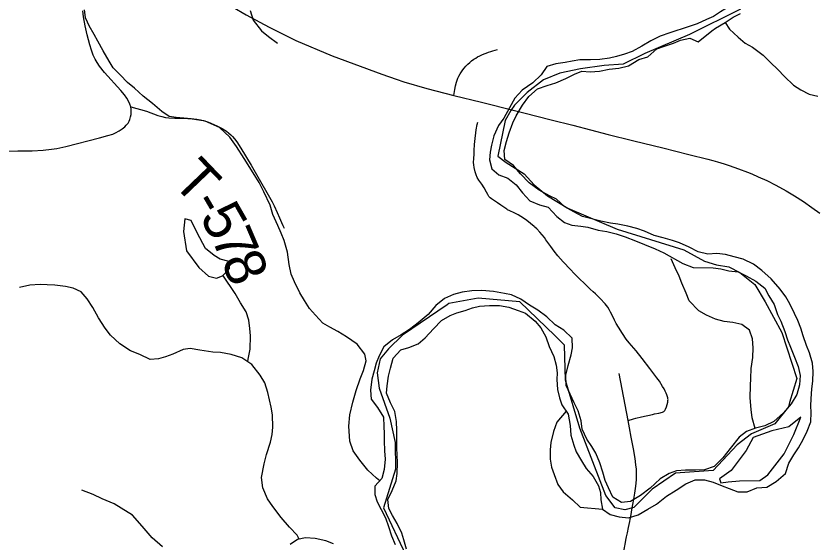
# Model space of a CAD drawing. Extents: x 1451455 to 1749751, y 218250 to 574981.
# Drawn here: x 1559745 to 1565644, y 318123 to 322002 of the extents above; entities that cross this region are included whole.
import ezdxf

# ---------------------------------------------------------------- set-up
doc = ezdxf.new("R2010")
doc.units = 0
for name, color, linetype in [('GM_X_County_Road', 7, 'Continuous'), ('GM_X_Major_River', 7, 'Continuous'), ('GM_X_Minor_Lake', 7, 'Continuous'), ('GM_X_Minor_River', 7, 'Continuous'), ('GM_X_State_Route', 7, 'Continuous'), ('GM_X_Township', 7, 'Continuous'), ('GM_X_Township_Road', 7, 'Continuous'), ('GM_X_Township_Road_Text', 7, 'Continuous'), ('GM_X_Township_ROW', 7, 'Continuous')]:
    doc.layers.add(name, color=color, linetype=linetype)

msp = doc.modelspace()

# ---------------------------------------------------------------- linework, layer by layer
at = {"layer": 'GM_X_County_Road'}
for points in [[(1560589.2, 321333.9), (1560583.5, 321352.9), (1560573.9, 321374.5), (1560560.8, 321397.8), (1560543.4, 321422.1), (1560517.9, 321452.6), (1560396.1, 321585.5), (1560360, 321631.9), (1560341.9, 321658.7), (1560327.5, 321684), (1560314.1, 321713.5), (1560300.5, 321750.1), (1560288, 321790.6), (1560269.7, 321863.6), (1560254.6, 321930.7), (1560242.7, 321994.9), (1560237.4, 322040.2)], [(1559488.5, 321004.8), (1559757.4, 321008.3), (1559862.6, 321010.4), (1559944.6, 321015), (1560007.2, 321022.2), (1560046, 321027.7), (1560110.4, 321041.4), (1560358.5, 321104), (1560422, 321121.4), (1560456.7, 321132.6), (1560478.1, 321141.7), (1560504.6, 321155.8), (1560527, 321170.4), (1560545.3, 321185.3), (1560557.1, 321197.3), (1560569.7, 321213.2), (1560577.8, 321228), (1560583.1, 321240.5), (1560588.7, 321259.9), (1560591.7, 321276.6), (1560593.2, 321296.7), (1560591.9, 321316.5), (1560589.2, 321333.9)]]:
    msp.add_lwpolyline(points, dxfattribs=at)
at = {"layer": 'GM_X_Major_River'}
for points in [[(1564997.1, 322072.7), (1564934.2, 322031.8), (1564881.6, 321998.7), (1564831.1, 321975.5), (1564760.5, 321944.8), (1564696, 321921.9), (1564559.6, 321877.9)], [(1564869.4, 321893.8), (1564896, 321912.3), (1564966.9, 321955.1), (1565027.6, 321994), (1565080.2, 322021.1)], [(1564559.6, 321877.9), (1564489.4, 321852.9), (1564421.1, 321819.9), (1564354.6, 321780.9), (1564282.2, 321741.9), (1564226, 321720.8), (1564167.8, 321703.6), (1564115.8, 321692.4), (1564045.8, 321681.5), (1563975.9, 321678.5), (1563898.1, 321679.7), (1563840, 321670.6), (1563790, 321659.3), (1563720, 321650.4), (1563653.8, 321631.4), (1563613, 321567.9), (1563550.2, 321510.8), (1563471.6, 321456), (1563418.8, 321396.7), (1563379.8, 321325.2), (1563338.7, 321249.8), (1563298, 321196.3), (1563264.9, 321120.7), (1563245.9, 321051), (1563237.1, 320999), (1563232.3, 320943), (1563249.2, 320876.7), (1563300.4, 320831.9), (1563365.9, 320808.8), (1563429.1, 320759.8), (1563474, 320699.1), (1563529, 320640.2), (1563600.4, 320611.1), (1563664, 320594.1), (1563728.9, 320527), (1563784.1, 320482.1), (1563837.7, 320463.3), (1563905.4, 320454.2), (1563957.2, 320447.4), (1564032.7, 320426.3), (1564096.4, 320415.3), (1564166, 320398.2), (1564231.5, 320377.2), (1564306.9, 320348), (1564374.3, 320318.9), (1564451.7, 320287.7), (1564517.1, 320258.7), (1564655.6, 320180.5), (1564731, 320151.3), (1564880.6, 320149), (1564936.4, 320140.2), (1564994, 320125.3), (1565063.8, 320118.2), (1565123.2, 320089.3), (1565194.5, 320050.1), (1565259.6, 319999.1), (1565290.6, 319942.6), (1565327.6, 319877.9), (1565354.4, 319805.5), (1565377.6, 319755), (1565406.4, 319678.5), (1565427.4, 319618.1), (1565448.5, 319563.8), (1565477.4, 319491.2), (1565504.3, 319422.7), (1565521.2, 319356.4), (1565516.2, 319286.4), (1565495.1, 319214.6), (1565454.2, 319147.2), (1565397.3, 319080), (1565326.5, 319017), (1565260.1, 318986), (1565192, 318967), (1565123.8, 318944), (1565071.2, 318900.7), (1565004.1, 318817.7), (1564951.2, 318750.4), (1564886.4, 318685.3), (1564816.2, 318662.3), (1564750.3, 318659.3), (1564676.4, 318658.5), (1564608.5, 318653.5), (1564556.3, 318634.3), (1564489.9, 318595.2), (1564415, 318526.3), (1564344.3, 318471.3), (1564271.8, 318428.4), (1564203.8, 318421.4), (1564140.6, 318460.4), (1564107.7, 318529), (1564084.5, 318583.4), (1564067.5, 318643.7), (1564044.6, 318712.2), (1564015.7, 318782.7), (1563984.6, 318833.2), (1563949.4, 318885.8), (1563914.6, 318960.4), (1563907.6, 319020.6), (1563884.8, 319095), (1563855.7, 319155.5), (1563826.7, 319218)], [(1564052.4, 318439.7), (1564065.4, 318371.5), (1564120.7, 318332.6), (1564188.2, 318315.5), (1564256, 318308.5), (1564328.2, 318329.4), (1564398.6, 318370.4), (1564463, 318407.4), (1564535.8, 318468.4), (1564606.3, 318511.4), (1564678.9, 318558.3), (1564747.2, 318587.3), (1564815, 318586.3), (1564878.6, 318569.3), (1564946.1, 318544.2), (1564997.7, 318523.4), (1565061.2, 318498.5), (1565129, 318499.4), (1565201.3, 318528.3), (1565275.2, 318533.2), (1565343.7, 318576.2), (1565412.5, 318635.3), (1565437.5, 318709), (1565474.4, 318770.5), (1565507.1, 318824), (1565542, 318885.6), (1565570.9, 318945.2), (1565599.8, 319014.8), (1565600.9, 319082.9), (1565599.6, 319133), (1565600.4, 319183), (1565605.5, 319257), (1565612.4, 319315), (1565615.4, 319385), (1565610.4, 319447.2), (1565589.6, 319521.6), (1565566.5, 319576), (1565541.6, 319648.4), (1565524.5, 319704.8), (1565503.4, 319761.1), (1565478.2, 319811.6), (1565443.4, 319884.2), (1565414.2, 319934.7), (1565373.2, 319991.4), (1565306.5, 320066.5), (1565237.6, 320129.6), (1565176.4, 320174.6), (1565101.1, 320211.8), (1565033.5, 320228.8), (1564969.9, 320245.8), (1564906.2, 320252.8), (1564840.2, 320247.8), (1564768.7, 320266.9), (1564703.3, 320299.9), (1564632, 320333), (1564580.4, 320349.8), (1564510.8, 320368.9), (1564445.2, 320385.9), (1564373.9, 320419), (1564318.2, 320437.9), (1564250.7, 320455), (1564177, 320470.1), (1564123.3, 320476.9), (1564051.6, 320492), (1563916.5, 320526.1), (1563853.1, 320561.1), (1563785.8, 320596.2), (1563724.8, 320653.2), (1563673.3, 320678), (1563598.1, 320719.2), (1563523.1, 320774.4), (1563460.2, 320839.4), (1563409.3, 320902.3), (1563344.1, 320945.3), (1563339.1, 321011.5), (1563358.1, 321079.3), (1563377, 321141.1), (1563404, 321214.7), (1563428.8, 321268.4), (1563473.9, 321345.8), (1563520.7, 321409.2), (1563585.5, 321466.2), (1563655.7, 321491.2), (1563721.8, 321510.2), (1563794.2, 321541.1), (1563858.5, 321574.2), (1563912.7, 321595.4), (1563974.5, 321590.5), (1564042.5, 321595.4), (1564112.5, 321610.4), (1564184.5, 321617.3), (1564256.6, 321634.2), (1564331.1, 321681.1), (1564397.3, 321702.1), (1564464.1, 321761.2), (1564514.2, 321778.4), (1564588.4, 321803.3), (1564638.7, 321824.6), (1564706.7, 321839.6), (1564768.2, 321812.6), (1564869.4, 321893.8)], [(1563826.7, 319218), (1563795.8, 319282.6), (1563795, 319358.7), (1563812, 319428.5), (1563833.2, 319508.3), (1563843.9, 319560.2), (1563841, 319630.3), (1563780, 319689.3), (1563714.8, 319728.3), (1563653.8, 319787.3), (1563588.7, 319836.4), (1563527.4, 319873.3), (1563462.2, 319916.4), (1563394.8, 319949.4), (1563343.1, 319960.2), (1563261.5, 319973.5), (1563175.8, 319980.8), (1563101.9, 319980), (1563031.9, 319969), (1562967.8, 319952), (1562901.5, 319923), (1562836.8, 319871.9), (1562779.9, 319804.7), (1562707.1, 319743.7), (1562642.5, 319694.7), (1562582.1, 319655.5), (1562517.6, 319618.5), (1562455, 319567.4), (1562420, 319499.9), (1562397.3, 319446.1), (1562382.5, 319390.3), (1562365.6, 319328.5), (1562356.4, 319248.6), (1562359.3, 319180.4), (1562406.3, 319119.6), (1562451.1, 319048.9), (1562454.1, 318980.8), (1562455.3, 318928.7), (1562456.5, 318874.6), (1562459.3, 318800.5), (1562462.4, 318738.4), (1562455.3, 318664.4), (1562438.3, 318596.6), (1562387.5, 318541.3), (1562388.6, 318479.2), (1562403.7, 318424.9), (1562434.8, 318368.4), (1562465.8, 318307.8), (1562488.8, 318243.4), (1562509.7, 318175), (1562536.7, 318110.5)], [(1562620, 318077.2), (1562601.1, 318145.6), (1562585.9, 318195.9), (1562553, 318266.5), (1562518, 318325), (1562490.8, 318377.5), (1562483.8, 318443.7), (1562514.8, 318509.3), (1562545.8, 318578.9), (1562552.6, 318634.9), (1562553.8, 318712.9), (1562552.7, 318771), (1562549.4, 318821.1), (1562548.4, 318887.2), (1562549.4, 318951.3), (1562546.4, 319017.4), (1562535.6, 319089.6), (1562502.6, 319154.2), (1562473.7, 319224.7), (1562478.6, 319280.7), (1562487.6, 319350.7), (1562502.5, 319410.5), (1562521.6, 319482.3), (1562578.4, 319543.5), (1562638.5, 319562.6), (1562706.8, 319589.6), (1562757.4, 319632.8), (1562820.2, 319700), (1562879, 319761.1), (1562941.5, 319798.2), (1562991.7, 319817.5), (1563053.8, 319834.5), (1563106, 319853.8), (1563158, 319865), (1563232, 319871.8), (1563305.8, 319870.7), (1563373.4, 319857.7), (1563443, 319834.6), (1563496.5, 319813.7), (1563569.5, 319756.6), (1563610.6, 319705.9), (1563647.5, 319639.2), (1563672.4, 319568.8), (1563705.2, 319496.2), (1563724.2, 319431.8), (1563729.4, 319375.7), (1563728.6, 319325.7), (1563733.5, 319253.5), (1563748.5, 319191.2), (1563765.7, 319138.9), (1563810.5, 319070.1), (1563825.3, 318987.8), (1563832.1, 318915.6), (1563853, 318843.2), (1563870.2, 318792.9), (1563909.1, 318726.2), (1563944.2, 318671.6), (1563995.2, 318612.8), (1564034.1, 318544.1), (1564049.3, 318493.8), (1564052.4, 318439.7)], [(1565011.7, 318657.4), (1564926.9, 318594.6), (1564936.5, 318566.4), (1564990.5, 318573.6), (1565072.4, 318580.4), (1565224.1, 318582.1), (1565282.6, 318623.2), (1565402.7, 318779.6), (1565474.7, 318920.6), (1565524.5, 319050)], [(1565524.5, 319050), (1565437.6, 318977.2), (1565311.4, 318947.1), (1565175, 318899.2), (1565123.7, 318803.8), (1565011.7, 318657.4)]]:
    msp.add_lwpolyline(points, dxfattribs=at)
at = {"layer": 'GM_X_Minor_Lake'}
for points in [[(1561265.8, 320090.4), (1561316.7, 320143.7), (1561313.5, 320193.8), (1561247.8, 320210.9), (1561204.3, 320239.6), (1561141.2, 320290.7), (1561079.2, 320405.8), (1561034.7, 320496.6), (1560988.9, 320509.4), (1560977.4, 320415.4), (1561001, 320272.9), (1561090.9, 320151.3), (1561161.8, 320086), (1561221.6, 320073.1)], [(1561221.6, 320073.1), (1561265.8, 320090.4)]]:
    msp.add_lwpolyline(points, dxfattribs=at)
at = {"layer": 'GM_X_Minor_River'}
for points in [[(1560245.9, 322048.4), (1560255, 321992.2), (1560284, 321927.6)], [(1561469.6, 322043.4), (1561490.5, 321970.9), (1561553.3, 321893.7), (1561604.7, 321850.8), (1561669.9, 321801.7)], [(1562424.2, 318581.2), (1562400.4, 318600.4), (1562335.4, 318659.5), (1562276.6, 318732.5), (1562227.8, 318801.4), (1562203, 318871.9), (1562194.8, 318982.2), (1562204.2, 319066.2), (1562225.7, 319160), (1562251.1, 319245.7), (1562280.5, 319331.3), (1562303.5, 319393.1), (1562322.7, 319462.9), (1562313.5, 319513.1), (1562256.8, 319586.1), (1562179.7, 319641.4), (1562114.4, 319678.5), (1562057, 319711.4), (1562003.5, 319740.3), (1561950.5, 319799.2), (1561905.4, 319850), (1561868.4, 319908.7), (1561835.3, 319963.3), (1561796.7, 320046), (1561771.7, 320102.5), (1561756.8, 320172.8), (1561744.3, 320263.1), (1561719.8, 320349.6), (1561698.7, 320404), (1561673.6, 320460.5), (1561637, 320541.2), (1561616.2, 320609.6), (1561569.8, 320706.5), (1561535, 320777.2), (1561478.5, 320868.2), (1561424, 320953.2), (1561367.4, 321040.2), (1561318.6, 321109.1), (1561243.9, 321182.3), (1561138.7, 321228.1), (1561059, 321241.3), (1561007.1, 321248.2), (1560923.3, 321255.5), (1560871.5, 321262.3), (1560818.1, 321299.2), (1560749.1, 321358.4), (1560682.1, 321411.6), (1560617.1, 321470.7), (1560565.8, 321513.5), (1560512.8, 321568.5), (1560459.7, 321619.4), (1560430.5, 321669.9), (1560385.8, 321744.7), (1560347, 321816.8), (1560320.9, 321865.4), (1560283, 321929.8)], [(1564966.9, 321955.1), (1565000, 321904.5), (1565063, 321845.4), (1565116.2, 321802.5), (1565169.7, 321771.6), (1565248.7, 321714.3), (1565301.7, 321659.4), (1565354.8, 321608.5), (1565406, 321557.7), (1565470.8, 321492.6), (1565524.2, 321457.7), (1565587.7, 321426.6), (1565649.4, 321411.7)], [(1565189.6, 318966.2), (1565165.6, 319043.9), (1565158.7, 319106.1), (1565152.1, 319192.3), (1565153.6, 319282.4), (1565156.4, 319334.4), (1565159.6, 319406.5), (1565171, 319488.4), (1565174.1, 319558.5), (1565169.3, 319626.6), (1565146.3, 319689.1), (1565091.1, 319732), (1565025.3, 319745.1), (1564959.5, 319754.1), (1564895.9, 319771.1), (1564830.4, 319800.2), (1564773, 319831.1), (1564702.2, 319904.3), (1564681.2, 319962.7), (1564648.4, 320035.3), (1564629.3, 320085.7), (1564600.3, 320148.3), (1564569.4, 320214.8)], [(1561451.4, 319455.9), (1561453.5, 319476.6), (1561468.7, 319548.4), (1561472.4, 319648.5), (1561467.3, 319702.7), (1561458.3, 319762.9), (1561439.3, 319823.3), (1561398.4, 319890), (1561359.6, 319958.8), (1561268.9, 320093.7)], [(1561829.3, 318151.1), (1561815.8, 318181), (1561758.9, 318240), (1561698, 318309), (1561635.4, 318390.1), (1561596.4, 318448.8), (1561561.8, 318529.5), (1561553.1, 318605.7), (1561572.7, 318705.6), (1561589.8, 318773.4), (1561619.3, 318865.1), (1561630.2, 318921), (1561637.1, 318974.9), (1561632.6, 319067.1), (1561623.5, 319121.4), (1561612.5, 319177.6), (1561599.3, 319229.9), (1561576.6, 319302.4), (1561543.5, 319357), (1561480.8, 319436.1), (1561407.7, 319485.3), (1561330.2, 319510.6), (1561250.5, 319525.8), (1561194.5, 319526.7), (1561098.9, 319542.2), (1561027.1, 319555.4), (1560977, 319546.2), (1560900.5, 319513.3), (1560846.2, 319492.2), (1560794, 319479), (1560732, 319474), (1560656.6, 319509.2), (1560589.1, 319536.3), (1560510.1, 319589.6), (1560441.2, 319652.8), (1560402, 319703.5), (1560351.3, 319780.4), (1560310.6, 319855.2), (1560267.7, 319919.9), (1560224.6, 319972.7), (1560165.1, 319999.7), (1560109.3, 320010.6), (1560029.5, 320019.9), (1559973.6, 320022.7), (1559921.7, 320025.6), (1559845.6, 320020.8), (1559769.4, 320004)], [(1563795.6, 319093), (1563728.2, 319012.2), (1563703.1, 318942.5), (1563683.8, 318862.7), (1563678.9, 318808.7), (1563679.7, 318740.6), (1563688.7, 318680.3), (1563707.8, 318626), (1563734.6, 318553.5), (1563775.7, 318498.7), (1563842.6, 318439.6), (1563899.7, 318386.6), (1564065.4, 318371.5)], [(1560823.1, 318094.5), (1560746.3, 318159.8), (1560673.8, 318247.1), (1560603.1, 318326.3), (1560518, 318377.7), (1560466.6, 318410.6), (1560379.3, 318448), (1560311.8, 318479.1), (1560230.4, 318512.5)], [(1562082.6, 318116.7), (1562027, 318139.6), (1561947.3, 318154.9), (1561877.5, 318160), (1561817.3, 318148.9), (1561762.7, 318111.7)]]:
    msp.add_lwpolyline(points, dxfattribs=at)
at = {"layer": 'GM_X_State_Route'}
for points in [[(1560081.5, 323088.5), (1560233.2, 322934), (1560434.3, 322738), (1560564.8, 322624.2), (1560761.5, 322462.5), (1560931.8, 322336), (1561139.4, 322194.3), (1561338.8, 322069.8), (1561440.5, 322011.1), (1561610.1, 321919.4), (1561806.8, 321822.6), (1562073.6, 321709.1), (1562439.6, 321574.3), (1562543.5, 321538.3)], [(1562543.5, 321538.3), (1562600.2, 321518.7), (1562769.6, 321468.5), (1562968.3, 321416.1), (1563174, 321367.2), (1563417.1, 321305.8), (1563483.9, 321288.9), (1563685.9, 321238.7), (1563845.4, 321198.2), (1564106.7, 321130.4), (1564285, 321084.8)], [(1564285, 321084.8), (1564294.8, 321082.3), (1564507.6, 321031.4), (1564701, 320983.3), (1564839.6, 320948.7), (1564875.8, 320938.6), (1564911.4, 320928.2), (1564960.2, 320913.4), (1564998.3, 320900.9), (1565065.9, 320877.7), (1565132.6, 320852.3), (1565164.7, 320839.2), (1565210.6, 320819.1), (1565274.3, 320790), (1565340.3, 320757), (1565418, 320715.7), (1565478.9, 320677.7), (1565545.4, 320636.3), (1565606.8, 320593.3), (1565664.9, 320551.4)]]:
    msp.add_lwpolyline(points, dxfattribs=at)
at = {"layer": 'GM_X_Township'}
msp.add_lwpolyline([(1565080, 322053), (1564704.7, 321866.7), (1564375.6, 321727), (1564217.7, 321647.4), (1564076.1, 321637.3), (1563902.5, 321613.5), (1563750.2, 321580.9), (1563629.9, 321532.7), (1563510.3, 321438), (1563415.6, 321345.3), (1563389.6, 321307), (1563346.7, 321233.7), (1563294.3, 320970.9), (1563355.2, 320922.7), (1563488.3, 320839.2), (1563560.4, 320758.5), (1563658.1, 320679.2), (1563809.6, 320587.2), (1564172, 320432.8), (1564663.1, 320281.3), (1564814.6, 320196.4), (1564903.8, 320170.9), (1564995.8, 320155.3), (1565075, 320112.8), (1565185.4, 320025), (1565263.3, 319899), (1565386.4, 319671.1), (1565496.9, 319332.7), (1565442.5, 319156.2), (1565433.2, 319126), (1565332.7, 318998.6), (1565162.8, 318924.9), (1565055.2, 318845.7), (1564878.3, 318657.3), (1564602.3, 318636.1), (1564430.6, 318517.8), (1564294.3, 318383.9), (1564228.3, 318366.5), (1564158.5, 318381.8), (1564088.5, 318471.9), (1563897.4, 318968.9), (1563791.2, 319321.4), (1563785.6, 319579.1), (1563712.4, 319649.4), (1563454.3, 319897.7), (1563148.6, 319924.6), (1562933.4, 319885), (1562919.5, 319875.5), (1562590.9, 319652.8), (1562489, 319552.3), (1562426.7, 319478.7), (1562405.5, 319375.3), (1562419.6, 319263.5), (1562497.5, 319041.2), (1562537.1, 318861.4), (1562540, 318666), (1562450.8, 318381.4), (1562615, 318031.7)], dxfattribs=at)
msp.add_lwpolyline([(1565080, 322053), (1564704.7, 321866.7), (1564375.6, 321727), (1564217.7, 321647.4), (1564076.1, 321637.3), (1563902.5, 321613.5), (1563750.2, 321580.9), (1563629.9, 321532.7), (1563510.3, 321438), (1563415.6, 321345.3), (1563389.6, 321307), (1563346.7, 321233.7), (1563294.3, 320970.9), (1563355.2, 320922.7), (1563488.3, 320839.2), (1563560.4, 320758.5), (1563658.1, 320679.2), (1563809.6, 320587.2), (1564172, 320432.8), (1564663.1, 320281.3), (1564814.6, 320196.4), (1564903.8, 320170.9), (1564995.8, 320155.3), (1565075, 320112.8), (1565185.4, 320025), (1565263.3, 319899), (1565386.4, 319671.1), (1565496.9, 319332.7), (1565442.5, 319156.2), (1565433.2, 319126), (1565332.7, 318998.6), (1565162.8, 318924.9), (1565055.2, 318845.7), (1564878.3, 318657.3), (1564602.3, 318636.1), (1564430.6, 318517.8), (1564294.3, 318383.9), (1564228.3, 318366.5), (1564158.5, 318381.8), (1564088.5, 318471.9), (1563897.4, 318968.9), (1563791.2, 319321.4), (1563785.6, 319579.1), (1563712.4, 319649.4), (1563454.3, 319897.7), (1563148.6, 319924.6), (1562933.4, 319885), (1562919.5, 319875.5), (1562590.9, 319652.8), (1562489, 319552.3), (1562426.7, 319478.7), (1562405.5, 319375.3), (1562419.6, 319263.5), (1562497.5, 319041.2), (1562537.1, 318861.4), (1562540, 318666), (1562450.8, 318381.4), (1562615, 318031.7)], dxfattribs=at)
at = {"layer": 'GM_X_Township_Road'}
for points in [[(1562968.3, 321416.1), (1562977.3, 321460.5), (1562982.8, 321487.8), (1562989.8, 321514.3), (1562999.9, 321543.5), (1563006.7, 321559.4), (1563016.2, 321577.2), (1563025.4, 321591.5), (1563036.2, 321606.7), (1563046.6, 321619.3), (1563058.3, 321632.8), (1563072.2, 321646.7), (1563087, 321661), (1563100.6, 321672), (1563117.3, 321684.4), (1563130.8, 321692.7), (1563144.2, 321700.6), (1563159.9, 321708.3), (1563176.5, 321716.5), (1563192.1, 321722.8), (1563207.6, 321729.1), (1563225.5, 321735.1), (1563242.8, 321740.9), (1563256.7, 321745.1), (1563291.2, 321754.3)], [(1560589.2, 321333.9), (1560706.1, 321300.5), (1560788.2, 321270.4), (1560818.3, 321261.3), (1560844.8, 321255.8), (1560870.4, 321252.1), (1560913.2, 321250.3), (1560977.2, 321249.4), (1561009.1, 321248.5), (1561033.8, 321247.6), (1561053.8, 321245.7), (1561077.6, 321243), (1561104, 321237.5), (1561125.9, 321232.1), (1561163.1, 321219.4), (1561178.4, 321213.6), (1561202.4, 321203.2), (1561227.8, 321191.4), (1561262.1, 321173.5), (1561294.7, 321153.6), (1561312.5, 321139.7), (1561327.2, 321127.5), (1561338.4, 321116), (1561354.8, 321097.2), (1561370.9, 321075.8), (1561401, 321029.1), (1561476.5, 320903.3), (1561534.5, 320801.5), (1561602.2, 320685.9), (1561631.5, 320634.6), (1561646.6, 320605.6), (1561669.2, 320554.7), (1561685.5, 320515.6), (1561698.9, 320482.7), (1561709.8, 320459.5), (1561719.2, 320440.2)], [(1564221.8, 317696.8), (1564206.5, 317797.6), (1564200.2, 317839.8), (1564198.3, 317862.6), (1564197.8, 317885.5), (1564199.6, 317914.9), (1564204.5, 317953.9), (1564209, 317983), (1564218.9, 318041.3), (1564222.4, 318060.6), (1564227.2, 318086.4), (1564229.9, 318102.6), (1564231.7, 318112.2), (1564237.2, 318144.3), (1564241.2, 318166.7), (1564247.4, 318198.5), (1564255.5, 318236.4), (1564264.9, 318280.7), (1564268.3, 318296.4), (1564274.9, 318331.6), (1564281.2, 318366.1)]]:
    msp.add_lwpolyline(points, dxfattribs=at)
at = {"layer": 'GM_X_Township_ROW'}
for points in [[(1564252.4, 319024.7), (1564292.3, 319035.9), (1564310.9, 319041.2), (1564352.4, 319050.5), (1564432.1, 319069.6), (1564447.7, 319073.3), (1564478.3, 319079.3), (1564505.3, 319085.4), (1564511.6, 319087.6), (1564516.6, 319091), (1564522.6, 319098.4), (1564527.2, 319106.5), (1564534.7, 319124.4), (1564541, 319142.9), (1564545, 319158.8), (1564546.6, 319171.8), (1564546.8, 319179.1), (1564546.2, 319184.8), (1564545.2, 319191.4), (1564543.8, 319197.6), (1564540.7, 319206.9), (1564538.1, 319212.8), (1564533.8, 319225.8), (1564527.1, 319241.1), (1564517.8, 319256.4), (1564507.1, 319274.4), (1564483.1, 319313.1), (1564464.4, 319339.1), (1564413.1, 319407.8), (1564357.1, 319481.1), (1564311.8, 319537.8), (1564261.1, 319595.1), (1564239.1, 319623.8), (1564212.4, 319664.5), (1564181.7, 319710.4), (1564165.7, 319739.1), (1564153.1, 319763.8), (1564137.8, 319795.8), (1564124.2, 319821.4), (1564114.4, 319842), (1564104.2, 319858.7), (1564083.3, 319883.8), (1564047.9, 319922.3), (1564012.8, 319956.4), (1563996.2, 319972.1), (1563974.6, 319992.1), (1563937.4, 320028.7), (1563890.3, 320072.7), (1563856.1, 320107.4), (1563828.9, 320135.6), (1563775.2, 320193.1), (1563736, 320237.2), (1563709, 320270.3), (1563683.7, 320304.5), (1563647.7, 320355.4), (1563636.2, 320371.2), (1563620.5, 320391.7), (1563603.9, 320411.1), (1563579.7, 320436), (1563566.1, 320448.4), (1563561.4, 320451.9), (1563533.9, 320474), (1563505.9, 320496.1), (1563490.7, 320508.2), (1563464, 320526.9), (1563444.2, 320538.3), (1563414.5, 320551.9), (1563381.7, 320566.6), (1563364.4, 320575.7), (1563358.8, 320579.1), (1563316.4, 320608.9), (1563290, 320627.6), (1563260.5, 320647.3), (1563247, 320656.3), (1563237, 320664.6), (1563228.1, 320674), (1563218.6, 320687.1), (1563208.9, 320704.1), (1563191.7, 320736.5), (1563175.3, 320763.7), (1563154.1, 320792.9), (1563142.4, 320812.6), (1563133.2, 320833.5), (1563126.3, 320855.3), (1563119, 320887), (1563116.2, 320906.3), (1563115.3, 320922.6), (1563116.9, 320952), (1563118.9, 320984.7), (1563119.9, 321020.7), (1563120.8, 321046.6), (1563121.4, 321056.3), (1563123.5, 321079), (1563133.9, 321163.6), (1563140.9, 321202.3), (1563145.4, 321221.4)], [(1564252.4, 319024.7), (1564186.9, 319370.4)], [(1564281.2, 318366.1), (1564295.6, 318444.6), (1564303.6, 318489.8), (1564310.1, 318541.9), (1564314, 318587.6), (1564315, 318626.9), (1564313.8, 318666.3), (1564310.9, 318698.9), (1564304.3, 318744.4), (1564291.7, 318815.2), (1564276.2, 318902.1), (1564262.8, 318969.5), (1564252.4, 319024.7)]]:
    msp.add_lwpolyline(points, dxfattribs=at)

# ---------------------------------------------------------------- texts
at = {"layer": 'GM_X_Township_Road_Text'}
for s, rotation, p in [('T', 313.76199, (1560886.7, 320774.8)), ('5', 299.74812, (1561092.5, 320521.8)), ('-', 300.28369, (1561030.7, 320627.6)), ('7', 293.24336, (1561180.1, 320369.4)), ('8', 292.44114, (1561252.6, 320200.6))]:
    msp.add_text(s, height=300, rotation=rotation, dxfattribs=at).set_placement(p)

doc.saveas('drawing.dxf')
